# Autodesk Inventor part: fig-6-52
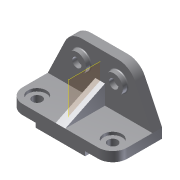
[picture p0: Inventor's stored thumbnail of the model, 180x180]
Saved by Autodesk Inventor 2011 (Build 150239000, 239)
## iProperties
Shininess: 77.0
Length Units: 11269
Angle Units: 11279
Time Units: 11290
Mass Units: 11283
Length Display Precision: 3
Angle Display Precision: 2
Created: 2001-12
Part Number: fig-6-52
Document SubType Name: Modeling
Designer: Renu Muthoo
Density: 1 g/cm^3
Density: 0.0
Volumn: 0.0
Area: 0.0
PropertySet Name: Model Information
Control State: 0
Master: False
Checked Out: False
Author: Renu Muthoo
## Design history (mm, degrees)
node "Sketch1"
sketch "Sketch2"
  geometry: L1 (-67.219, 19.116)-(148.781, 19.116); L2 (148.781, 19.116)-(148.781, -0.884); L3 (-67.219, -0.884)-(-67.219, 19.116); L4 (-10.219, -0.884)-(-10.219, -9.884); L5 (-10.219, -9.884)-(91.781, -9.884); L6 (91.781, -9.884)-(91.781, -0.884); L7 (148.781, -0.884)-(91.781, -0.884); L8 (-10.219, -0.884)-(-67.219, -0.884)
  constraints: 16 end point, 5 parallel, 4 perpendicular, 2 equal length, 1 horizontal
  dimensions: "d0" = 102 distance of L4.end L5.end; "d1" = 57 distance of L4.start L3.start; "d2" = 29 distance between parallel lines of L1 L5; "d3" = 20 distance of L1.end L2.end
extrude "Extrusion1" new body sketch "Sketch2" distance "d4" = 102; taper "d5" = 0 deg
sketch "Sketch3"
  geometry: L1 (67.219, -19.116)-(-148.781, -19.116) reference; L2 (67.219, -19.116)-(31.475, -93.564); L3 (-2.781, -115.116)-(-78.781, -115.116); L4 (-113.038, -93.564)-(-148.781, -19.116); A1 r 38 centre (-2.781, -77.116) between (-2.781, -115.116) and (31.475, -93.564); A2 r 38 centre (-78.781, -77.116) between (-113.038, -93.564) and (-78.781, -115.116)
  constraints: 6 end point, 4 point on circle, 4 tangent, 2 centre point, 1 equal length, 1 equal radius, 1 parallel
  dimensions: "d6" = 96 distance between parallel lines of L3 L1; "d7" = 38 radius of A1; "d8" = 76 distance of A2.centre A1.centre
extrude "Extrusion2" join sketch "Sketch3" distance "d9" = 20; taper "d10" = 0 deg
fillet "Fillet1" dims "d11" = 30
workplane "Work Plane1"
sketch "Sketch5"
  geometry: A1 r 30 centre (-30, 0) between (-30, -30) and (0, 0) reference; 1 further point
  constraints: 1 coincident
hole "Hole1" sketch "Sketch5" at (-30, 0) diameter "d16" = 20; stored, may be unused: countersink angle "d20" = 82 deg, drill point angle "d22" = 118 deg; dims "d17" = 6, "d18" = 38, "d19" = 6, "d21" = 8
sketch "Sketch6"
  geometry: C1 r 19 at (-2.781, 77.116); C2 r 9.5 at (-2.781, 77.116); A1 r 38 centre (-2.781, 77.116) between (31.475, 93.564) and (-2.781, 115.116) reference
  constraints: 2 centre point, 2 coincident
  dimensions: "d23" = 38 diameter of C1; "d24" = 19 diameter of C2
extrude "Extrusion3" join sketch "Sketch6" distance "d25" = 10; taper "d26" = 0 deg
sketch "Sketch7"
  geometry: L1 (0, -82)-(-39.557, 0); L2 (0, -82)-(20, -82) reference; L3 (29, 22.405)-(29, -82); L4 (29, -82)-(0, -82); L5 (0, -82)-(0, 0); L6 (0, 0)-(-90.034, 0); L7 (-90.034, 0)-(-90.034, 22.405); L8 (-90.034, 22.405)-(29, 22.405); L9 (0, 0)-(-74.447, 0) reference
  constraints: 14 end point, 1 collinear, 1 point on line
feature "Rib3" sketch "Sketch7" dims "d35" = 10, "d36" = 20
fillet "Fillet3" dims "d37" = 2
mirror "Mirror4"
body "Solid1"
other parameters: "d12" = -108
